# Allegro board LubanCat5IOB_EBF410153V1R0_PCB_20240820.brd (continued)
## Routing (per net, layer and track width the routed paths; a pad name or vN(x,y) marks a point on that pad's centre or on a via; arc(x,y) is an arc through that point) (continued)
I2C5_SCL_M3: length 267.7
  TOP w0.152: v1(47.28,32.16) 45.96,32.16 45.69,32.43 45.69,36.51 45.26,36.95 30.94,36.95 30.43,37.45 30.43,42.31 29.99,42.74 29.99,60.3 29.44,60.85 9.75,60.85 7.65,62.96 7.65,67.15 7.34,67.45 5.4,67.45 4.44,67.45 3.68,68.21 3.68,72.74 3.99,73.04 5.5,73.04 v1(5.97,72.57) ; R358.2 85.09,16.3 v2(85.64,16.85) 86.04,17.25 J2.92
  ART03 w0.152: v1(47.28,32.16) 47.79,31.64 57.61,31.64 60.07,29.17 63.65,29.17 64.14,29.66 76.1,29.66 76.89,30.44 v2(85.17,30.44)
  ART04 w0.152: v2(85.17,30.44) 85.17,17.33 v2(85.64,16.85)
  BOTTOM w0.152: v2(85.64,16.85) 86.48,16.02 93.88,16.02 95.28,14.62 123.52,14.62 127.88,18.98 140.6,18.98 141.42,19.8 141.42,29.22 141.72,29.52 157.19,29.52 157.56,29.89 157.56,30.94 157.99,31.38 169.53,31.38 170.55,32.4 170.55,54.32 169.91,54.96 J35.6 ; J15.9 v1(5.97,72.57)
I2C5_SDA_M3: length 267.1
  TOP w0.152: v1(48.28,32.16) 47.8,32.63 46.43,32.63 46.2,32.86 46.2,36.97 45.75,37.43 31.24,37.43 30.89,37.78 30.89,42.48 30.38,42.99 30.38,60.75 29.77,61.36 10.06,61.36 8.05,63.36 8.05,67.48 7.58,67.96 4.66,67.96 4.19,68.42 4.19,72.28 4.48,72.57 v1(4.97,72.57) ; J2.94 v2(86.44,17.69) 86.44,16.73 86.11,16.4 R359.2
  ART03 w0.152: v1(87.73,31.51) 77.06,31.51 75.67,30.11 64.01,30.11 63.83,30.29 59.84,30.29 57.98,32.16 v1(48.28,32.16)
  ART04 w0.152: v1(87.73,31.51) 87.73,31.51 86.44,30.22 v2(86.44,17.69)
  BOTTOM w0.152: J15.10 5.47,73.07 v1(4.97,72.57) ; v2(86.44,17.69) 86.44,16.83 86.87,16.4 95.28,16.4 95.69,15.99 111.56,15.99 112.39,15.15 122.45,15.15 126.73,19.43 140.41,19.43 140.97,19.99 140.97,29.67 141.27,29.97 156.74,29.97 157.05,30.28 157.05,31.52 157.4,31.88 169.42,31.88 170.05,32.51 170.05,54.11 169.71,54.46 J35.5
I2C7_SCL: length 36.5
  TOP w0.152: Q34.3 140.68,36.66 v1(140.72,36.7) ; J36.6 164.36,44.06 163.96,44.46 159.87,44.46 159.38,43.98 v1(159.38,37.46)
  BOTTOM w0.152: v1(159.38,37.46) 158.75,38.1 141.04,38.1 140.72,37.77 v1(140.72,36.7)
  BOTTOM w0.173: R331.2 v1(140.72,36.7)
I2C7_SCL_M0: length 195.8
  TOP w0.152: J2.77 83.24,23.39 83.39,23.54 83.39,31.18 v1(82.6,31.97) ; Q34.2 v1(142.71,36.66) ; U16.28 v1(19.1,78.37)
  ART03 w0.152: v1(82.6,31.97) 100.56,31.97 104.17,28.36 139.22,28.36 141.99,31.13 141.99,35.94 v1(142.71,36.66)
  ART04 w0.152: v1(82.6,31.97) 83.67,31.97 84.61,32.91 84.61,45.58 84.18,46.01 50.85,46.01 50.06,45.23 42.39,45.23 41.63,45.99 41.63,66.56 38.61,69.59 38.61,72.46 38.3,72.76 32.13,72.76 31.32,73.57 22.83,73.57 21.97,74.44 21.97,79.64 21.67,79.95 18.87,79.95 18.52,79.59 18.52,78.95 v1(19.1,78.37)
  BOTTOM w0.173: v1(142.71,36.66) 142.75,36.63 R332.2
I2C7_SDA: length 31.9
  TOP w0.152: Q33.3 v1(144.61,36.66) ; v1(158.39,37.46) 158.39,44.49 158.8,44.91 164.15,44.91 164.49,44.56 J36.5
  BOTTOM w0.152: v1(158.39,37.46) 145.41,37.46 v1(144.61,36.66)
  BOTTOM w0.173: v1(144.61,36.66) 144.78,36.5 R330.2
I2C7_SDA_M0: length 195.5
  TOP w0.152: v1(19.1,79.37) 19.55,78.92 U16.27 ; J2.75 82.84,28.66 82.5,29 82.5,31.28 82.14,31.64 v1(82.14,33.82) 82.14,41.95 v1(81.64,42.46) ; Q33.2 v1(146.65,36.66)
  ART03 w0.152: v1(82.14,33.82) 102.46,33.82 102.87,34.23 116.81,34.23 v1(117.59,33.44)
  ART04 w0.152: v1(81.64,42.46) 82.17,41.92 83.67,41.92 84.02,42.28 84.02,45.18 83.59,45.61 51.41,45.61 50.62,44.82 42.21,44.82 41.27,45.76 41.27,62.4 40.21,63.46 40.21,67.4 38.2,69.41 38.2,72.1 37.9,72.4 31.57,72.4 30.94,73.04 22.63,73.04 22,73.67 21.55,73.67 20.95,74.27 20.95,78.86 20.44,79.37 v1(19.1,79.37)
  BOTTOM w0.152: v1(117.59,33.44) 119.5,31.54 131.09,31.54 133.4,33.85 138.91,33.85 139.61,33.15 142.62,33.15 143.13,33.65 145.67,33.65 146.05,34.03 146.05,34.91 R329.2
  BOTTOM w0.173: R329.2 146.69,36.63 v1(146.65,36.66)
I2C8_SCL_M2: length 100.7
  TOP w0.152: J2.96 86.84,17.25 v2(87.24,16.85) 87.12,16.73 R356.2
  BOTTOM w0.152: J37.6 163.02,37.56 160.81,35.35 148.56,35.35 148.26,35.04 148.26,31.33 147.79,30.86 140.26,30.86 139.95,30.56 139.95,20.62 139.65,20.32 125.79,20.32 122.43,16.96 96.5,16.96 95.28,18.18 87.17,18.18 86.87,17.87 86.87,17.22 v2(87.24,16.85)
I2C8_SDA_M2: length 99.8
  TOP w0.152: R357.2 87.74,16.15 87.74,17.19 v2(87.24,17.69) J2.98
  BOTTOM w0.152: J37.5 163.13,37.06 160.99,34.91 148.97,34.91 148.67,34.61 148.67,30.93 148.1,30.36 140.8,30.36 140.45,30.01 140.45,20.12 140.15,19.82 126.15,19.82 122.05,15.71 112.62,15.71 111.91,16.42 96.03,16.42 95.13,17.32 87.61,17.32 v2(87.24,17.69)
I2S0_LRCK: length 119.5
  TOP w0.152: v1(82.64,43.46) 85.03,43.46 85.72,42.76 85.72,28.11 84.84,27.22 J2.85 ; v1(17.65,74.26) 17.75,74.36 U16.7
  ART04 w0.152: v1(17.65,74.26) 18.14,73.77 18.14,70.68 18.57,70.25 27.64,70.25 28.55,69.33 34.34,69.33 35.13,68.54 35.13,67.2 36.55,65.78 36.55,45.79 40.61,41.72 67.79,41.72 68.07,42 80.75,42 81.05,42.31 81.05,42.64 81.36,42.94 82.12,42.94 v1(82.64,43.46)
I2S0_MCLK: length 118.7
  TOP w0.152: J2.81 84.04,23.54 83.9,23.69 83.9,41.2 v1(82.64,42.46) ; U16.1 17.85,77.06 v1(17.65,77.26)
  ART04 w0.152: v1(17.65,77.26) 17.65,76.85 21.34,73.17 21.77,73.17 22.43,72.51 30.71,72.51 31.32,71.9 37.21,71.9 37.52,71.59 37.52,69.36 38.4,68.47 38.4,67.71 39.7,66.41 39.7,63.24 40.16,62.78 40.16,46.12 41.96,44.31 50.95,44.31 51.71,45.07 82.98,45.07 83.41,44.64 83.41,42.86 83.01,42.46 v1(82.64,42.46)
I2S0_SCLK: length 116.6
  TOP w0.152: J2.83 84.44,42.35 83.87,42.92 80.18,42.92 v1(79.64,43.46) ; U16.5 v1(17.65,75.26)
  ART04 w0.152: v1(17.65,75.26) 19.92,72.99 19.92,72.02 20.23,71.72 20.68,71.72 21.07,71.33 28.51,71.33 28.96,70.88 35.97,70.88 36.2,70.65 36.2,69.2 36.77,68.63 36.77,67.56 38.23,66.1 38.23,45.66 41.05,42.84 66.88,42.84 67.5,43.46 v1(79.64,43.46)
I2S0_SDI0: length 120.2
  TOP w0.152: v1(80.64,43.46) 81.67,44.49 85.78,44.49 86.69,43.58 86.69,27.68 85.64,26.63 J2.89 ; U16.8 19.1,73.41 18.94,73.26 v1(18.65,73.26)
  ART04 w0.152: v1(18.65,73.26) 19.05,72.86 19.05,70.93 19.23,70.75 27.86,70.75 28.75,69.86 31.55,69.86 32.03,70.35 34.92,70.35 35.23,70.04 35.23,69.38 35.73,68.89 35.73,67.46 37.49,65.7 37.49,61.71 37.26,61.48 37.26,45.84 40.82,42.28 67.21,42.28 67.79,42.86 80.05,42.86 v1(80.64,43.46)
I2S0_SDO0: length 124.9
  TOP w0.152: v1(81.64,43.46) 82.19,44.01 85.42,44.01 86.26,43.17 86.26,27.9 85.24,26.89 J2.87 ; v1(17.65,73.26) 17.14,73.76 17.14,74.56 17.39,74.81 U16.6
  ART04 w0.152: v1(81.64,43.46) 81.09,44.01 66.52,44.01 66.01,43.5 54.25,43.5 53.95,43.8 41.66,43.8 39.14,46.32 39.14,65.9 37.27,67.77 37.27,68.88 36.7,69.45 36.7,71.08 36.4,71.39 30.96,71.39 30.4,71.95 22.25,71.95 21.54,72.66 21.08,72.66 17.87,75.88 17.21,75.88 16.92,75.58 16.92,73.56 17.22,73.26 v1(17.65,73.26)
LCD0_BL_PWM: length 143.2
  TOP w0.152: J4.85 84.84,63.92 v2(84.44,63.52) ; J14.13 v1(8.13,77.07)
  ART04 w0.152: v1(29.09,78.45) 31.03,78.45 31.48,78.91 38.33,78.91 38.73,79.31 38.73,85.74 41.53,88.53 47.83,88.53 48.13,88.23 48.13,86.76 49.4,85.49 49.4,84.6 48.13,83.33 48.13,72.68 48.44,72.38 50.45,72.38 50.75,72.07 50.75,70.85 51.03,70.58 52.91,70.58 54.33,69.15 54.33,55.36 55.63,54.07 72.85,54.07 73.53,54.75 73.53,68.24 74.42,69.13 79.48,69.13 79.78,68.82 79.78,68.49 80.09,68.19 81.39,68.19 81.62,67.96 81.62,66.32 82.14,65.8 82.91,65.8 83.16,65.55 85.31,65.55 85.61,65.24 85.61,64.2 85.31,63.9 84.82,63.9 v2(84.44,63.52)
  BOTTOM w0.152: v1(8.13,77.07) 8.29,77.07 9.83,75.53 11.19,75.53 11.7,76.03 11.7,76.25 11.95,76.51 12.26,76.51 13.26,77.51 16.48,77.51 17.04,78.07 17.58,78.07 18.34,78.83 22.68,78.83 22.89,78.63 28.91,78.63 v1(29.09,78.45)
LCD0_PWR_EN: length 130.6
  TOP w0.152: v1(79.6,41.47) 79.64,41.43 79.64,29.48 79.17,29.01 79.17,27.85 79.4,27.62 79.4,23.31 79.64,23.07 J2.59
  ART03 w0.152: v1(34.21,43.04) 35.05,42.2 78.89,42.2 79.6,41.49 v1(79.6,41.47)
  BOTTOM w0.152: R306.1 12.95,81.47 13.26,81.17 22.94,81.17 23.62,81.85 34.85,81.85 35.26,81.45 35.26,64.28 34.82,63.85 33.48,63.85 33.12,63.49 33.12,57.39 33.58,56.94 33.58,43.68 v1(34.21,43.04)
LCD0_RST: length 166.6
  TOP w0.152: v1(125.78,44.33) 125.78,47.39 126.09,47.69 132.09,47.69 132.39,47.39 U44.18 ; J14.15 6.09,76.07 5.58,75.56 3.28,75.56 2.92,75.21 2.92,62.78 3.35,62.35 6.55,62.35 10.03,58.87 10.03,52.86 v1(9.58,52.4)
  ART03 w0.152: v1(125.78,44.33) 123.63,46.48 117.59,46.48 117.22,46.12 108.58,46.12 107.52,45.05 100.05,45.05 98.78,46.32 37.26,46.32 36.17,47.41 30.25,47.41 29.57,48.1 21.08,48.1 20.85,47.87 11.43,47.87 11.02,48.27 11.02,48.99 10.79,49.21 10.79,52.08 10.47,52.4 v1(9.58,52.4)
LCD1_BL_PWM: length 139.7
  TOP w0.152: J4.87 v2(85.24,64.36)
  ART04 w0.152: v1(29.09,77.45) 31.03,77.45 31.44,77.87 38.79,77.87 39.27,78.35 39.27,85.64 41.53,87.9 45.59,87.9 47.24,86.25 47.24,81.68 46.74,81.17 46.74,74.31 47.12,73.93 47.12,72.15 47.35,71.92 49.48,71.92 49.78,71.62 49.78,70.47 50.09,70.17 52.68,70.17 53.9,68.95 53.9,54.9 55.19,53.61 73.1,53.61 73.93,54.44 73.93,68.08 74.63,68.77 78.94,68.77 79.25,68.47 79.25,67.58 79.53,67.3 80.54,67.3 80.85,66.99 80.85,65.67 81.25,65.27 82.7,65.27 83.06,64.91 84.69,64.91 v2(85.24,64.36)
  BOTTOM w0.152: J15.13 7.95,74.57 8.18,74.79 8.18,75.55 8.46,75.83 8.91,75.83 9.57,75.17 11.84,75.17 13.23,76.57 16.23,76.57 17.35,77.69 18.19,77.69 18.52,77.36 19.68,77.36 20.27,77.94 22.76,77.94 23.09,77.61 28.93,77.61 v1(29.09,77.45)
LCD1_PWR_EN: length 93.6
  TOP w0.152: R305.1 28.19,64.03 28.38,63.84 29.62,63.84 30.26,63.2 33.49,63.2 v1(33.67,63.39) ; J2.61 80.04,23.3 79.76,23.59 79.76,27.6 80.04,27.88 80.04,42.06 v1(79.64,42.46)
  ART03 w0.152: v1(34.21,44.19) 35.64,42.76 79.34,42.76 v1(79.64,42.46)
  BOTTOM w0.152: v1(33.67,63.39) 33.53,63.24 33.53,58.05 34.16,57.42 34.16,44.24 v1(34.21,44.19)
LCD1_RST: length 172.1
  TOP w0.152: U44.20 133.69,48.39 133.38,48.71 124.09,48.71 123.78,48.4 v1(123.78,44.33)
  ART03 w0.152: v1(9.58,50.4) 9.58,47.06 10.03,46.6 25.22,46.6 25.55,46.27 35.23,46.27 35.97,45.53 97.43,45.53 100.28,42.69 103.3,42.69 103.86,43.25 108,43.25 109.33,44.58 123.54,44.58 v1(123.78,44.33)
  BOTTOM w0.152: v1(9.58,50.4) 9.07,50.91 9.07,56.79 8.71,57.15 7.52,57.15 6.5,58.16 5.03,58.16 4.72,58.47 4.72,59.66 4.37,60.02 2.69,60.02 2.29,60.43 2.29,75.18 2.67,75.56 7,75.56 J15.15
LOUT1: length 50.1
  TOP w0.203: U16.12 20.9,72.68 v1(21.32,72.26)
  ART03 w0.203: v1(36.59,90.45) 36.59,91.04 36.04,91.58 20.5,91.58 19.84,90.92 19.84,87.87 19.46,87.49 19.46,85.51 20.14,84.83 22.35,84.83 22.99,84.19 22.99,83.07 23.22,82.84 23.22,81.85 22.81,81.45 20.37,81.45 19.61,80.69 19.61,77.79 19.08,77.26 19.08,70.91 19.28,70.7 20.98,70.7 21.32,71.04 v1(21.32,72.26)
  BOTTOM w0.203: C122.1 36.79,90.65 v1(36.59,90.45)
LOUT2: length 10.4
  TOP w0.203: C279.1 26.42,68.34 23.88,68.34 23.62,68.59 23.62,73.55 22.81,74.36 U16.15
M2EKEY_3V3: length 18.8
  ART04 w0.254: 131.1,75.3 v1(131.1,74.54)
  BOTTOM w0.254: v1(131.1,74.54) 131.1,77.43 130.43,78.1 128.4,78.1 128.02,77.72 R147.1 ; 158.52,63.27 158,62.75 156.01,62.75 155.75,62.5 155.75,57.29 156.13,56.91 C128.2 R138.2
  vias: v1(123.7,62.39) v1(124.7,62.39) v1(141.4,66.38) v1(141.4,65.38) v1(159.57,64.46) v1(159.57,63.46) v1(160.57,64.46) v1(160.57,63.46)
M2EKEY_NWDISABLE: length 124.7
  TOP w0.152: v2(82.44,17.69) J2.74
  ART03 w0.152: v2(82.96,29.56) 87.96,29.56 89.28,30.88 100.14,30.88 103.57,27.45 140.51,27.45 143.63,30.57 143.63,37.21 145.4,38.97 145.4,56.68 145.09,56.99 135.41,56.99 135.1,57.29 135.1,59.41 134.8,59.71 128.7,59.71 v1(128.27,59.28)
  ART04 w0.152: v2(82.96,29.56) 82.96,18.21 v2(82.44,17.69)
  BOTTOM w0.152: R146.2 v1(128.27,59.28)
M2EKEY_PWR_EN: length 143.4
  TOP w0.152: v1(164.62,15.21) 164.62,31.13 164.31,31.43 156.54,31.43 156.24,31.74 156.24,45.23 155.93,45.53 154.91,45.53 154.64,45.81 154.64,48.89 154.97,49.22 155.3,49.22 155.57,49.5 155.57,51.89 155.23,52.23 155.23,53.42 v1(155.68,53.86) ; v2(80.84,17.69) J2.66
  BOTTOM w0.152: v2(80.84,17.69) 81.24,17.29 83.52,17.29 83.95,16.86 83.95,15.48 86.08,13.35 87.88,13.35 91.19,10.05 155.46,10.05 156.08,10.67 156.08,13.66 156.39,13.97 163.37,13.97 v1(164.62,15.21) ; R140.2 v1(155.68,53.86)
M2PCIE_3V3: length 24.8
  TOP w0.254: R237.2 v1(161.04,81.43) ; J19.2 152.03,86.45 C170.1 C171.1 ; C182.1 154.07,82.32 R236.2 ; J19.74 v1(170.04,85.3) ; C181.1 v1(157.11,81.42) ; J19.72 v1(169.54,87.62) ; J19.70 v1(169.04,85.3)
  ART03 w0.254: v1(158.11,81.42) 158.11,80.42 v1(158.11,80.42) v1(157.11,80.42) v1(157.11,81.42) ; v1(151.03,80.42) v1(151.03,81.42)
  ART04 w0.254: v1(151.32,72.36) 151.32,80.13 v1(151.03,80.42)
  BOTTOM w0.254: v1(151.32,72.36) 151.37,72.4 C157.2 R218.2
  vias: v1(151.03,83.42) v1(151.03,82.42)
M2PCIE_PWR_EN: length 146.1
  TOP w0.152: v1(150.32,69.36) 147.21,69.36 146.94,69.09 146.94,56.48 146.38,55.92 v1(144.45,55.92) ; v1(67.64,48.22) 65.96,48.22 65.53,47.79 65.53,38.04 65.23,37.73 53.58,37.73 53.27,37.43 J1.55
  ART03 w0.152: v1(67.64,48.22) 67.72,48.15 76.1,48.15 76.28,48.33 76.28,49.11 76.58,49.42 80.72,49.42 81.1,49.04 84.02,49.04 84.93,49.94 116.14,49.94 116.92,49.16 123.14,49.16 123.47,49.49 144.15,49.49 144.45,49.8 v1(144.45,55.92)
  BOTTOM w0.152: R221.2 v1(150.32,69.36)
M2PCIE_REF_CLKN: length 108.9
  TOP w0.114: J19.53 164.79,92.98 164.92,92.85 164.92,89.05 v1(164.63,88.76)
  BOTTOM w0.114: v1(164.63,88.76) 164.85,88.98 arc(164.9,89.06) 164.92,89.15 164.92,89.85 arc(165.06,90.19) 165.39,90.32 165.74,90.32 arc(166.07,90.19) 166.2,89.85 166.2,88.46 arc(166.09,87.86) 165.75,87.35 163.58,85.18 163.33,84.94 arc(163.08,84.56) 162.99,84.11 162.99,80.71 arc(162.86,80.04) 162.48,79.48 161.96,78.95 arc(161.53,78.67) 161.02,78.56 158.95,78.56 arc(158.23,78.42) 157.61,78.01 157.53,77.92 156.65,77.04 arc(155.91,76.55) 155.04,76.38 154.46,76.38 arc(153.64,76.22) 152.96,75.75 150.29,73.09 arc(149.48,71.88) 149.2,70.45 149.2,66.63 149.17,66.27 148.65,63.28 149.17,60.29 149.2,59.93 149.2,55.1 arc(149.09,54.53) 148.76,54.05 147.49,52.78 147.48,52.76 arc(147.07,52.49) 146.58,52.39 139.08,52.39 arc(139.07,52.39) 139.05,52.39 135.6,51.79 arc(135.52,51.78) 135.44,51.79 132,52.39 arc(131.98,52.39) 131.96,52.39 129.52,52.39 arc(128.68,52.22) 127.97,51.75 126.98,50.76 arc(126.38,50.36) 125.68,50.22 118.03,50.22 arc(118.01,50.22) 117.99,50.21 114.59,49.62 arc(114.51,49.62) 114.43,49.62 111.03,50.21 arc(111.01,50.22) 110.99,50.22 110.59,50.22 arc(110.57,50.22) 110.55,50.21 106.01,49.43 arc(105.93,49.42) 105.85,49.43 arc(105.84,49.43) 105.83,49.43 arc(105.82,49.43) 105.81,49.43 100.79,49.43 100.33,48.98 100.33,46.45 100.56,46.22 101.73,46.22 v1(102.12,46.61)
M2PCIE_REF_CLKP: length 108.9
  TOP w0.114: J19.55 165.29,92.98 165.16,92.85 165.16,89.99 arc(165.2,89.91) 165.28,89.87 arc(165.37,89.83) 165.4,89.75 165.4,89.53 arc(165.37,89.45) 165.28,89.41 arc(165.2,89.38) 165.16,89.29 165.16,89.05 v1(165.45,88.76)
  BOTTOM w0.114: v1(102.12,45.59) 101.73,45.98 100.46,45.98 100.09,46.35 100.09,49.08 100.69,49.67 105.81,49.67 arc(105.85,49.67) 105.89,49.67 arc(105.93,49.66) 105.97,49.66 110.51,50.45 arc(110.55,50.46) 110.59,50.46 110.99,50.46 arc(111.03,50.46) 111.07,50.45 114.47,49.86 arc(114.51,49.86) 114.55,49.86 117.95,50.45 arc(117.99,50.46) 118.03,50.46 125.68,50.46 arc(126.29,50.58) 126.81,50.93 127.8,51.92 arc(128.59,52.45) 129.52,52.63 131.96,52.63 arc(132,52.63) 132.04,52.62 135.48,52.03 arc(135.52,52.02) 135.56,52.03 139,52.62 arc(139.04,52.63) 139.08,52.63 146.58,52.63 arc(146.98,52.71) 147.31,52.93 147.32,52.95 148.59,54.22 arc(148.86,54.62) 148.96,55.1 148.96,59.92 148.93,60.26 148.4,63.28 148.93,66.3 148.96,66.64 148.96,70.45 arc(149.26,71.97) 150.12,73.26 152.79,75.93 arc(153.55,76.44) 154.46,76.62 155.04,76.62 arc(155.82,76.77) 156.48,77.21 157.36,78.09 157.44,78.18 arc(158.14,78.64) 158.95,78.81 161.02,78.81 arc(161.43,78.89) 161.79,79.12 162.31,79.65 arc(162.64,80.14) 162.75,80.71 162.75,84.11 arc(162.86,84.65) 163.16,85.11 163.41,85.35 165.58,87.52 arc(165.86,87.95) 165.96,88.46 165.96,89.85 arc(165.9,90.02) 165.74,90.08 165.39,90.08 arc(165.23,90.02) 165.16,89.85 165.16,89.15 arc(165.18,89.06) 165.23,88.98 v1(165.45,88.76)
MASKROM: length 6.8
  TOP w0.152: R1.1 25.92,14.87 D2.2 ; SW1.2 27.34,11.54 26.93,11.94 D2.2 ; D2.2 C4.1
MDIN0_PHY0: length 1.8
  TOP w0.114: U4.2 71.86,80.75 71.94,80.84 71.94,81.15 72.31,81.52 72.32,81.52 72.32,81.71 R366.1
MDIN0_PHY0_RJ45: length 7.8
  TOP w0.114: R366.2 72.32,82.66 72.32,83.08 73.2,83.96 75.14,83.96 75.37,84.19 75.37,85.84 75.14,86.07 74.53,86.07 74.3,85.84 J6.3
MDIN0_PHY1: length 1.8
  TOP w0.114: R374.1 53.92,81.71 53.92,81.52 53.91,81.52 53.54,81.15 53.54,80.84 53.46,80.75 U3.2
MDIN0_PHY1_RJ45: length 8.1
  TOP w0.114: R374.2 53.92,82.66 53.92,83.08 54.29,83.45 56.74,83.45 56.97,83.68 56.97,85.84 56.74,86.07 56.13,86.07 55.9,85.84 J7.3
MDIN1_PHY0: length 1.8
  TOP w0.114: R368.1 71.03,81.73 71.03,81.56 70.74,81.27 70.74,80.85 70.66,80.77 U4.5
MDIN1_PHY0_RJ45: length 13.9
  TOP w0.114: R368.2 70.85,82.78 71.05,82.98 71.05,83.55 71.56,84.06 72.24,84.06 72.93,84.76 72.93,85.66 71.68,86.92 71.68,88.55 71.44,88.79 69.4,88.79 69.22,88.61 J6.7
MDIN1_PHY1: length 1.8
  TOP w0.114: U3.5 52.26,80.77 52.34,80.85 52.34,81.27 52.63,81.56 52.63,81.73 R376.1
MDIN1_PHY1_RJ45: length 14
  TOP w0.114: R376.2 52.45,82.78 52.65,82.98 52.65,83.55 53.16,84.06 53.84,84.06 54.53,84.76 54.53,85.66 53.28,86.92 53.28,88.69 53.14,88.83 51.11,88.83 50.82,88.53 J7.7
MDIN2_PHY0: length 1.7
  TOP w0.114: U4.7 69.86,80.76 69.94,80.84 69.94,81.24 69.78,81.4 69.78,81.71 R370.1
MDIN2_PHY0_RJ45: length 5.7
  TOP w0.114: R370.2 69.58,82.78 69.78,82.98 69.78,83.4 70.32,83.94 70.32,87.58 J6.6
MDIN2_PHY1: length 1.7
  TOP w0.114: R378.1 51.38,81.71 51.38,81.4 51.54,81.24 51.54,80.84 51.46,80.76 U3.7
MDIN2_PHY1_RJ45: length 5.7
  TOP w0.114: J7.6 51.92,87.58 51.92,83.94 51.38,83.4 51.38,82.98 51.18,82.78 R378.2
MDIN3_PHY0: length 1.7
  TOP w0.114: R372.1 68.49,81.73 68.49,81.4 68.72,81.16 68.72,80.84 68.66,80.78 U4.10
MDIN3_PHY0_RJ45: length 5.7
  TOP w0.114: J6.9 66.68,85.83 66.87,86.02 67.71,86.02 67.9,85.83 67.9,84.06 68.51,83.46 68.51,82.98 68.31,82.78 R372.2
MDIN3_PHY1: length 1.7
  TOP w0.114: R380.1 50.09,81.73 50.09,81.4 50.32,81.16 50.32,80.84 50.26,80.78 U3.10
MDIN3_PHY1_RJ45: length 5.7
  TOP w0.114: R380.2 49.91,82.78 50.11,82.98 50.11,83.46 49.5,84.06 49.5,85.79 49.28,86.02 48.51,86.02 48.28,85.79 J7.9
MDIP0_PHY0: length 1.8
  TOP w0.114: U4.1 72.26,80.78 72.18,80.85 72.18,81.05 72.41,81.28 72.42,81.28 72.56,81.42 72.56,81.71 R365.1
MDIP0_PHY0_RJ45: length 7.8
  TOP w0.114: R365.2 72.56,82.66 72.56,82.98 73.3,83.72 75.24,83.72 75.61,84.09 75.61,87.71 J6.2
MDIP0_PHY1: length 1.8
  TOP w0.114: U3.1 53.86,80.78 53.78,80.85 53.78,81.05 54.01,81.28 54.02,81.28 54.16,81.42 54.16,81.71 R373.1
MDIP0_PHY1_RJ45: length 8.1
  TOP w0.114: R373.2 54.16,82.66 54.16,82.98 54.39,83.21 56.84,83.21 57.21,83.58 57.21,87.71 J7.2
MDIP1_PHY0: length 1.8
  TOP w0.114: U4.4 71.06,80.76 70.98,80.84 70.98,81.17 71.27,81.46 71.27,81.69 R367.1
MDIP1_PHY0_RJ45: length 13.9
  TOP w0.114: R367.2 71.49,82.78 71.29,82.98 71.29,83.45 71.66,83.82 72.34,83.82 73.18,84.66 73.18,85.76 71.92,87.02 71.92,88.65 71.54,89.03 71.01,89.03 70.82,89.22 70.82,89.68 70.94,89.8 72.72,89.8 73.03,89.49 J6.4
MDIP1_PHY1: length 1.8
  TOP w0.114: R375.1 52.87,81.69 52.87,81.46 52.58,81.17 52.58,80.84 52.66,80.76 U3.4
MDIP1_PHY1_RJ45: length 14
  TOP w0.114: J7.4 54.63,89.45 54.3,89.78 52.57,89.78 52.35,89.56 52.35,89.28 52.57,89.07 53.24,89.07 53.52,88.79 53.52,87.02 54.78,85.76 54.78,84.66 53.94,83.82 53.26,83.82 52.89,83.45 52.89,82.98 53.09,82.78 R375.2
MDIP2_PHY0: length 1.7
  TOP w0.114: R369.1 70.03,81.72 70.03,81.5 70.18,81.34 70.18,80.85 70.26,80.77 U4.6
MDIP2_PHY0_RJ45: length 5.7
  TOP w0.114: J6.5 71.76,85.88 71.6,86.04 70.72,86.04 70.56,85.88 70.56,83.84 70.02,83.3 70.02,82.98 70.22,82.78 R369.2
MDIP2_PHY1: length 1.7
  TOP w0.114: U3.6 51.86,80.77 51.78,80.85 51.78,81.34 51.63,81.5 51.63,81.72 R377.1
MDIP2_PHY1_RJ45: length 5.7
  TOP w0.114: J7.5 53.36,85.85 53.17,86.04 52.35,86.04 52.16,85.85 52.16,83.84 51.62,83.3 51.62,82.98 51.82,82.78 R377.2
MDIP3_PHY0: length 1.8
  TOP w0.114: U4.9 69.06,80.72 68.96,80.82 68.96,81.26 68.74,81.48 68.74,81.71 R371.1
MDIP3_PHY0_RJ45: length 5.7
  TOP w0.114: J6.8 68.15,87.55 68.15,84.16 68.75,83.56 68.75,82.98 68.95,82.78 R371.2
MDIP3_PHY1: length 1.8
  TOP w0.114: R379.1 50.34,81.71 50.34,81.48 50.56,81.26 50.56,80.82 50.66,80.72 U3.9
MDIP3_PHY1_RJ45: length 5.7
  TOP w0.114: J7.8 49.75,87.55 49.75,84.16 50.35,83.56 50.35,82.98 50.55,82.78 R379.2
MIC1N: length 41.8
  TOP w0.152: C113.2 v1(20.45,82.31)
  BOTTOM w0.152: v1(20.45,82.31) 20.14,82.62 20.14,83.05 20.45,83.35 22.17,83.35 23.06,84.24 39.75,84.24 43.03,87.52 43.03,92.83 43.71,93.52 43.71,96.91 43.15,97.47 38.8,97.47 R117.2
MIC1P: length 42.4
  TOP w0.152: C112.2 v1(19.43,82.31)
  BOTTOM w0.152: v1(19.43,82.31) 19.79,82.67 19.79,83.19 20.3,83.71 22.02,83.71 22.91,84.6 39.6,84.6 42.67,87.67 42.67,92.98 43.36,93.66 43.36,96.76 43,97.12 38.14,97.12 R114.2
MIC2N: length 23.2
  TOP w0.152: C117.2 v1(22.48,82.31) ; R134.2 v1(3.94,86.88)
  ART03 w0.152: v1(3.94,86.88) 3.63,86.58 3.63,85.81 4.01,85.44 8.43,85.44 10.41,83.45 21.9,83.45 22.2,83.15 22.2,82.59 v1(22.48,82.31)
MIC2P: length 23.3
  TOP w0.152: C115.2 v1(21.46,82.31) ; R130.2 v1(2.92,86.88)
  ART03 w0.152: v1(2.92,86.88) 3.28,86.53 3.28,85.66 3.86,85.08 8.28,85.08 10.26,83.1 21.69,83.1 21.84,82.95 21.84,82.69 v1(21.46,82.31)
MINIPCIE_3V3: length 45.9
  TOP w0.254: J23.39 126.1,73.21 125.77,73.54 v1(125.76,73.54) 125.74,73.54 125.3,73.1 J23.41
  TOP w0.381: v1(144.91,60.32) C223.1 J23.2 ; J23.24 132.1,60.34 C221.1 131.49,60.32 v1(131.32,60.49) v1(130.52,60.49) ; C220.1 120.9,63.88 J23.52
  ART04 w0.254: v1(144.53,77.98) 144.53,76.25 144.93,75.84 148.18,75.84 148.69,75.34 148.69,66.22 149.2,65.72 v1(150.08,65.72)
  ART04 w0.508: v1(125.76,74.56) v1(125.76,73.54)
  BOTTOM w0.254: R254.1 C200.1 151.85,57.22 150.34,57.22 150.09,57.47 150.09,62.68 150.34,62.93 151.7,62.93 C203.1 ; R264.1 v1(144.53,77.98)
  vias: v1(122.78,60.32) v1(123.78,60.32) v1(144.91,61.32) v1(150.08,64.72) v1(150.08,63.72) v1(150.83,65.72) v1(150.83,64.72) v1(150.83,63.72)
MINIPCIE_NWDISABLE: length 88.9
  TOP w0.152: v2(76.45,66.18) 76.04,66.6 J4.42 ; R267.2 v1(134.11,58.55)
  ART03 w0.152: v1(75.78,48.63) 75.78,49.42 76.17,49.8 79.12,49.8 79.54,50.21 80.04,50.21 80.35,49.9 80.93,49.9 81.34,49.49 83.67,49.49 84.66,50.48 128.7,50.48 129.72,51.5 133.43,51.5 134.11,52.19 v1(134.11,58.55)
  ART04 w0.152: v1(75.78,48.63) 77.24,50.09 77.24,65.39 v2(76.45,66.18)
MINIPCIE_PWR_EN: length 110.9
  TOP w0.152: v1(150.13,53.7) 149.56,53.7 149.17,53.31 149.17,43.25 149.52,42.9 151.21,42.9 151.59,42.52 v1(151.59,40.89) ; J2.71 82.04,22.74 82.42,23.12 82.42,28.46 82.02,28.87 82.02,31.03 81.64,31.41 81.64,41.45 v1(81.64,41.46)
  ART03 w0.152: v1(113.84,43.18) 113.22,42.56 110.36,42.56 107.82,40.02 83.08,40.02 v1(81.64,41.46)
  BOTTOM w0.152: v1(150.13,53.7) 150.29,53.86 R262.1 ; v1(113.84,43.18) 114.81,42.2 130.05,42.2 130.75,41.5 150.98,41.5 v1(151.59,40.89)
MIPI_CSI0_CLK0N: length 167.5
  TOP w0.114: v2(66.29,22.39) 66.51,22.17 66.51,19.15 65.28,17.92 65.28,16.02 63.14,13.88 52.86,13.88 52.39,14.34 52.39,17.96 52.47,18.04 J1.52 ; v1(164.39,59.3) 164.68,59.59 165.01,59.59 165.14,59.46 J34.10
  ART03 w0.102: v2(66.29,22.39) 66.59,22.69 66.59,23.04 66.96,23.41 67.24,23.41 arc(67.32,23.44) 67.35,23.52 arc(67.39,23.6) 67.47,23.64 67.65,23.64 arc(67.73,23.6) 67.76,23.52 arc(67.79,23.44) 67.87,23.41 68.05,23.41 arc(68.13,23.44) 68.17,23.52 arc(68.2,23.6) 68.28,23.64 68.46,23.64 arc(68.54,23.6) 68.57,23.52 arc(68.61,23.44) 68.69,23.41 68.87,23.41 arc(68.95,23.44) 68.98,23.52 arc(69.01,23.6) 69.09,23.64 69.27,23.64 arc(69.35,23.6) 69.39,23.52 arc(69.42,23.44) 69.5,23.41 69.68,23.41 arc(69.76,23.44) 69.79,23.52 arc(69.83,23.6) 69.91,23.64 70.08,23.64 arc(70.17,23.6) 70.2,23.52 arc(70.23,23.44) 70.31,23.41 70.49,23.41 arc(70.57,23.44) 70.6,23.52 arc(70.64,23.6) 70.72,23.64 70.9,23.64 arc(70.98,23.6) 71.01,23.52 arc(71.04,23.44) 71.13,23.41 100.01,23.41 102.71,20.72 114.92,20.72 116.85,22.65 148.39,22.65 149.1,23.36 149.1,28.32 149.76,28.99 149.76,34.9 149.45,35.21 149.45,52.97 149.82,53.34 152.7,53.34 153.87,54.51 157.05,54.51 157.25,54.71 157.25,58.45 157.65,58.85 161.89,58.85 162.33,58.41 162.33,57.9 162.53,57.7 163.47,57.7 163.97,58.19 164.97,58.19 165.19,58.41 165.19,59.36 164.98,59.57 164.66,59.57 v1(164.39,59.3)
MIPI_CSI0_CLK0P: length 167.5
  TOP w0.114: v1(164.39,60.11) 164.68,59.83 165.01,59.83 165.14,59.96 J34.9 ; J1.50 52.07,18.04 52.15,17.96 52.15,14.24 52.76,13.64 63.24,13.64 65.52,15.92 65.52,17.82 66.75,19.05 66.75,22.07 v2(67.07,22.39)
  ART03 w0.102: v1(164.39,60.11) 164.66,59.85 165.1,59.85 165.47,59.48 165.47,58.29 165.09,57.91 164.08,57.91 163.59,57.42 162.42,57.42 162.05,57.78 162.05,58.29 161.78,58.57 157.76,58.57 157.53,58.33 157.53,54.59 157.16,54.23 153.99,54.23 152.82,53.06 149.94,53.06 149.73,52.86 149.73,35.32 150.04,35.02 150.04,28.87 149.38,28.21 149.38,23.24 148.5,22.37 116.97,22.37 115.04,20.44 102.59,20.44 99.9,23.13 67.07,23.13 66.87,22.93 66.87,22.59 v2(67.07,22.39)
MIPI_CSI0_CLK1N: length 168.9
  TOP w0.114: v2(49.44,20.29) 49.18,20.03 49.18,19.71 49.27,19.61 J1.36
  ART03 w0.102: v1(164.34,57.11) 164.07,56.85 163.33,56.85 162.89,56.4 162.89,56.11 162.76,55.99 162.76,55.71 162.89,55.58 162.89,55.3 162.76,55.17 162.76,54.89 162.89,54.77 162.89,54.49 162.76,54.36 162.76,54.08 162.89,53.95 162.89,53.68 162.76,53.55 162.76,53.27 162.89,53.14 162.89,50.71 162.52,50.34 153.83,50.34 153.03,49.55 153.03,16.4 152.16,15.52 140.61,15.52 139.22,16.91 126.19,16.91 125.07,15.79 93.24,15.79 93.04,15.99 93.04,18.07 92.66,18.46 55.13,18.46 54.76,18.09 54.76,16.07 54.56,15.86 49.5,15.86 49.19,16.18 49.19,20.04 v2(49.44,20.29)
  BOTTOM w0.114: v1(164.34,57.11) 164.63,56.83 165.01,56.83 165.14,56.96 J35.10
MIPI_CSI0_CLK1P: length 168.9
  TOP w0.114: v2(48.66,20.29) 48.94,20.01 48.94,19.68 48.87,19.61 J1.34
  ART03 w0.102: v1(164.34,56.3) 164.07,56.57 163.45,56.57 163.17,56.29 163.17,50.6 162.63,50.06 153.94,50.06 153.31,49.43 153.31,16.28 152.27,15.24 140.49,15.24 139.1,16.63 126.3,16.63 125.19,15.51 93.13,15.51 92.76,15.88 92.76,17.96 92.54,18.18 55.24,18.18 55.04,17.97 55.04,15.95 54.67,15.59 49.39,15.59 48.91,16.07 48.91,20.04 v2(48.66,20.29)
  BOTTOM w0.114: v1(164.34,56.3) 164.63,56.59 165.01,56.59 165.14,56.46 J35.9
MIPI_CSI0_D0N: length 167.6
  TOP w0.114: J34.12 165.14,58.46 165.01,58.59 163.1,58.59 v1(162.81,58.3) ; v2(63.92,24.55) 64.19,24.28 64.19,19.5 63.25,18.56 63.25,16.65 62.18,15.59 55.08,15.59 54.39,16.27 54.39,17.96 54.47,18.04 J1.62
  ART03 w0.102: v2(63.92,24.55) 64.18,24.82 64.18,25.83 64.63,26.28 73.89,26.28 74.4,25.77 101.13,25.77 102.2,24.7 107.05,24.7 107.33,24.42 107.33,23.88 107.45,23.76 107.62,23.76 107.74,23.88 107.74,24.52 108.02,24.81 108.42,24.81 108.71,24.52 108.71,23.88 108.83,23.76 108.99,23.76 109.11,23.88 109.11,24.42 109.4,24.7 146.34,24.7 146.74,25.1 146.74,28.58 147.62,29.47 147.62,54.74 148.23,55.35 151.99,55.35 153.15,56.5 155.22,56.5 155.42,56.71 155.42,61.45 155.79,61.81 163.2,61.81 163.85,61.16 163.85,58.93 163.49,58.57 163.08,58.57 v1(162.81,58.3)
MIPI_CSI0_D0P: length 167.6
  TOP w0.114: v2(64.7,24.55) 64.43,24.28 64.43,19.4 63.49,18.46 63.49,16.55 62.28,15.34 54.98,15.34 54.15,16.17 54.15,17.96 54.07,18.04 J1.60 ; v1(162.81,59.11) 163.1,58.83 165.01,58.83 165.14,58.96 J34.11
  ART03 w0.102: v1(162.81,59.11) 163.08,58.85 163.37,58.85 163.57,59.05 163.57,61.05 163.09,61.53 155.91,61.53 155.7,61.33 155.7,56.59 155.34,56.23 153.27,56.23 152.11,55.07 148.35,55.07 147.9,54.63 147.9,29.35 147.02,28.46 147.02,24.98 146.46,24.42 109.51,24.42 109.39,24.31 109.39,23.77 109.11,23.48 108.71,23.48 108.43,23.77 108.43,24.41 108.31,24.53 108.14,24.53 108.02,24.41 108.02,23.77 107.74,23.48 107.34,23.48 107.06,23.77 107.06,24.31 106.94,24.42 102.08,24.42 101.02,25.49 74.28,25.49 73.77,26 67.19,26 arc(67.13,25.97) 67.1,25.91 arc(67.07,25.85) 67.01,25.82 66.78,25.82 arc(66.72,25.85) 66.69,25.91 arc(66.67,25.97) 66.6,26 66.38,26 arc(66.31,25.97) 66.29,25.91 arc(66.26,25.85) 66.2,25.82 65.97,25.82 arc(65.91,25.85) 65.88,25.91 arc(65.85,25.97) 65.79,26 65.56,26 arc(65.5,25.97) 65.47,25.91 arc(65.45,25.85) 65.38,25.82 65.16,25.82 arc(65.09,25.85) 65.07,25.91 arc(65.04,25.97) 64.98,26 64.74,26 64.46,25.72 64.46,24.79 v2(64.7,24.55)
MIPI_CSI0_D1N: length 167.5
  TOP w0.114: J34.8 165.14,60.46 165.01,60.59 162.34,60.59 v1(162.05,60.3) ; v2(65.1,23.33) 65.37,23.06 65.37,19.41 64.26,18.3 64.26,16.27 62.71,14.72 54.13,14.72 53.59,15.26 53.59,17.96 53.67,18.04 J1.58
  ART03 w0.102: v2(65.1,23.33) 65.33,23.56 65.33,24.18 65.7,24.55 66.03,24.55 arc(66.11,24.58) 66.14,24.67 arc(66.17,24.75) 66.25,24.78 66.43,24.78 arc(66.51,24.75) 66.55,24.67 arc(66.58,24.58) 66.66,24.55 66.84,24.55 arc(66.92,24.58) 66.95,24.67 arc(66.99,24.75) 67.07,24.78 67.24,24.78 arc(67.33,24.75) 67.36,24.67 arc(67.39,24.58) 67.47,24.55 67.65,24.55 arc(67.73,24.58) 67.77,24.67 arc(67.8,24.75) 67.88,24.78 68.06,24.78 arc(68.14,24.75) 68.17,24.67 arc(68.2,24.58) 68.29,24.55 68.46,24.55 arc(68.54,24.58) 68.58,24.67 arc(68.61,24.75) 68.69,24.78 68.87,24.78 arc(68.95,24.75) 68.98,24.67 arc(69.02,24.58) 69.1,24.55 69.28,24.55 arc(69.36,24.58) 69.39,24.67 arc(69.42,24.75) 69.5,24.78 69.68,24.78 arc(69.76,24.75) 69.8,24.67 arc(69.83,24.58) 69.91,24.55 100.58,24.55 102.46,22.67 109.85,22.67 109.97,22.79 109.97,23.63 110.25,23.92 110.65,23.92 110.94,23.63 110.94,22.79 111.06,22.67 111.22,22.67 111.34,22.79 111.34,23.63 111.63,23.92 112.03,23.92 112.31,23.63 112.31,22.79 112.43,22.67 114.48,22.67 115.29,23.48 147.66,23.48 148.16,23.98 148.16,28.55 148.51,28.91 148.51,53.49 149.36,54.34 152.32,54.34 153.48,55.5 156.16,55.5 156.36,55.7 156.36,59.45 156.73,59.82 162.55,59.82 162.81,60.08 162.81,60.36 162.61,60.57 162.32,60.57 v1(162.05,60.3)
MIPI_CSI0_D1P: length 167.5
  TOP w0.114: J1.56 53.27,18.04 53.35,17.96 53.35,15.16 54.03,14.48 62.81,14.48 64.5,16.17 64.5,18.2 65.61,19.31 65.61,23.06 v2(65.88,23.33) ; J34.7 165.14,60.96 165.01,60.83 162.34,60.83 v1(162.05,61.11)
  ART03 w0.102: v1(162.05,61.11) 162.32,60.85 162.72,60.85 163.09,60.48 163.09,59.96 162.67,59.54 156.84,59.54 156.64,59.33 156.64,55.59 156.27,55.22 153.59,55.22 152.43,54.06 149.48,54.06 148.79,53.38 148.79,28.79 148.44,28.44 148.44,23.87 147.78,23.21 115.41,23.21 114.59,22.39 112.31,22.39 112.03,22.68 112.03,23.52 111.91,23.64 111.74,23.64 111.62,23.52 111.62,22.68 111.34,22.39 110.94,22.39 110.66,22.68 110.66,23.52 110.54,23.64 110.37,23.64 110.25,23.52 110.25,22.68 109.97,22.39 102.35,22.39 100.47,24.27 65.81,24.27 65.61,24.07 65.61,23.6 v2(65.88,23.33)
MIPI_CSI0_D2N: length 168.9
  TOP w0.114: v2(51.44,20.29) 51.18,20.03 51.18,19.71 51.27,19.61 J1.46
  ART03 w0.102: v1(161.54,58.11) 161.28,57.85 161.05,57.85 arc(160.98,57.88) 160.95,57.95 arc(160.92,58.02) 160.85,58.05 160.65,58.05 arc(160.57,58.02) 160.54,57.95 arc(160.51,57.88) 160.44,57.85 160.24,57.85 arc(160.17,57.88) 160.14,57.95 arc(160.11,58.02) 160.04,58.05 159.83,58.05 arc(159.76,58.02) 159.73,57.95 arc(159.7,57.88) 159.63,57.85 158.56,57.85 158.19,57.48 158.19,52.54 157.99,52.34 150.87,52.34 150.49,51.96 150.49,48.09 150.88,47.7 150.88,18.44 150.25,17.82 141.77,17.82 140.32,19.27 123.99,19.27 122.59,17.87 116.39,17.87 116.27,17.99 116.27,18.35 115.99,18.63 115.59,18.63 115.31,18.35 115.31,17.99 115.19,17.87 115.02,17.87 114.9,17.99 114.9,18.35 114.62,18.63 114.22,18.63 113.94,18.35 113.94,17.99 113.82,17.87 113.65,17.87 113.53,17.99 113.53,18.35 113.25,18.63 112.85,18.63 112.56,18.35 112.56,17.99 112.45,17.87 112.22,17.87 112.01,18.07 112.01,19.03 111.65,19.4 106.95,19.4 106.58,19.03 106.58,18.07 106.38,17.87 95.12,17.87 95.02,17.97 95.02,20.77 94.59,21.2 52.89,21.2 52.53,20.83 52.53,19.57 52.32,19.37 51.39,19.37 51.19,19.57 51.19,20.04 v2(51.44,20.29)
  BOTTOM w0.114: v1(161.54,58.11) 161.83,57.83 165.01,57.83 165.14,57.96 J35.12
MIPI_CSI0_D2P: length 168.9
  TOP w0.114: J1.44 50.87,19.61 50.94,19.68 50.94,20.01 v2(50.66,20.29)
  ART03 w0.102: v2(50.66,20.29) 50.91,20.04 50.91,19.46 51.27,19.09 52.44,19.09 52.81,19.46 52.81,20.72 53.01,20.92 94.47,20.92 94.74,20.65 94.74,17.86 95.01,17.59 106.49,17.59 106.86,17.96 106.86,18.91 107.06,19.12 111.53,19.12 111.73,18.91 111.73,17.96 112.1,17.59 112.56,17.59 112.84,17.87 112.84,18.23 112.96,18.35 113.13,18.35 113.25,18.23 113.25,17.87 113.53,17.59 113.93,17.59 114.22,17.87 114.22,18.23 114.33,18.35 114.5,18.35 114.62,18.23 114.62,17.87 114.9,17.59 115.3,17.59 115.59,17.87 115.59,18.23 115.71,18.35 115.87,18.35 115.99,18.23 115.99,17.87 116.28,17.59 122.71,17.59 124.1,18.99 140.21,18.99 141.66,17.54 150.37,17.54 151.16,18.33 151.16,47.82 150.77,48.21 150.77,51.84 150.98,52.06 158.1,52.06 158.47,52.43 158.47,57.37 158.67,57.57 161.27,57.57 v1(161.54,57.3)
  BOTTOM w0.114: J35.11 165.14,57.46 165.01,57.59 161.83,57.59 v1(161.54,57.3)
MIPI_CSI0_D3N: length 168.8
  TOP w0.114: v2(50.69,17.37) 50.41,17.65 50.41,17.98 50.47,18.04 J1.42
  ART03 w0.102: v2(50.69,17.37) 50.44,17.12 50.44,16.83 50.64,16.63 50.87,16.63 arc(51,16.68) 51.05,16.8 arc(51.1,16.93) 51.22,16.98 51.28,16.98 arc(51.4,16.93) 51.45,16.8 arc(51.51,16.68) 51.63,16.63 53.19,16.63 53.39,16.83 53.39,18.93 53.83,19.37 93.57,19.37 94.06,18.89 94.06,17.26 94.26,17.06 107.25,17.06 107.37,17.18 107.37,18.43 107.66,18.71 108.06,18.71 108.34,18.43 108.34,17.18 108.46,17.06 108.63,17.06 108.75,17.18 108.75,18.43 109.03,18.71 109.43,18.71 109.71,18.43 109.71,17.18 109.83,17.06 110.06,17.06 110.18,17.18 110.18,18.22 110.46,18.51 110.86,18.51 111.14,18.22 111.14,17.18 111.26,17.06 123.68,17.06 124.52,17.9 140,17.9 140.97,16.93 151.79,16.93 152.04,17.19 152.04,49.79 153.6,51.34 158.82,51.34 159.28,51.81 159.28,55.17 159.9,55.79 161.22,55.79 v1(161.54,56.11)
  BOTTOM w0.114: v1(161.54,56.11) 161.83,55.83 165.01,55.83 165.14,55.96 J35.8
MIPI_CSI0_D3P: length 168.8
  TOP w0.114: J1.40 50.07,18.04 50.17,17.95 50.17,17.62 v2(49.91,17.37)
  ART03 w0.102: v1(161.54,55.3) 161.33,55.51 160.02,55.51 159.56,55.06 159.56,51.69 158.93,51.06 153.71,51.06 152.32,49.67 152.32,17.07 151.91,16.65 140.85,16.65 139.89,17.62 124.64,17.62 123.8,16.78 111.15,16.78 110.86,17.06 110.86,18.11 110.74,18.23 110.58,18.23 110.46,18.11 110.46,17.06 110.17,16.78 109.71,16.78 109.43,17.06 109.43,18.31 109.31,18.43 109.14,18.43 109.02,18.31 109.02,17.06 108.74,16.78 108.34,16.78 108.06,17.06 108.06,18.31 107.94,18.43 107.77,18.43 107.65,18.31 107.65,17.06 107.37,16.78 94.14,16.78 93.78,17.15 93.78,18.77 93.46,19.09 53.95,19.09 53.67,18.81 53.67,16.71 53.3,16.35 50.53,16.35 50.16,16.71 50.16,17.12 v2(49.91,17.37)
  BOTTOM w0.114: v1(161.54,55.3) 161.83,55.59 165.01,55.59 165.14,55.46 J35.7
MIPI_CSI1_CLK0N: length 172.3
  TOP w0.114: J1.41 50.47,23.05 v2(50.07,23.45) ; v1(161.54,41.91) 161.83,42.19 165.01,42.19 165.14,42.06 J36.10
  ART03 w0.102: v2(50.07,23.45) 49.79,23.17 49.65,23.17 47.1,23.17 46.61,22.68 46.61,14.65 47.65,13.6 64.86,13.6 65.38,14.12 65.38,14.9 65.58,15.1 65.98,15.1 66.1,14.98 66.1,14.32 66.39,14.04 81.51,14.04 82.68,15.2 90.36,15.2 90.7,14.86 90.7,12.17 91.11,11.76 147.66,11.76 147.94,12.04 147.94,12.68 148.06,12.8 148.23,12.8 148.35,12.68 148.35,12.04 148.63,11.76 149.03,11.76 149.31,12.04 149.31,12.68 149.43,12.8 149.6,12.8 149.72,12.68 149.72,12.04 150,11.76 150.4,11.76 150.69,12.04 150.69,12.68 150.8,12.8 150.97,12.8 151.09,12.68 151.09,12.04 151.37,11.76 151.89,11.76 155.7,15.57 155.7,41.97 155.96,42.23 161.22,42.23 v1(161.54,41.91)
MIPI_CSI1_CLK0P: length 172.3
  TOP w0.114: J36.9 165.14,42.56 165.01,42.43 161.83,42.43 v1(161.54,42.72) ; J1.39 v2(50.07,22.61)
  ART03 w0.102: v2(50.07,22.61) 49.79,22.89 49.51,22.89 49.28,22.89 arc(49.2,22.86) 49.17,22.78 arc(49.13,22.7) 49.06,22.67 48.87,22.67 arc(48.79,22.7) 48.76,22.78 arc(48.73,22.86) 48.65,22.89 48.46,22.89 arc(48.39,22.86) 48.35,22.78 arc(48.32,22.7) 48.24,22.67 48.06,22.67 arc(47.98,22.7) 47.95,22.78 arc(47.92,22.86) 47.84,22.89 47.22,22.89 46.89,22.56 46.89,14.76 47.77,13.88 64.74,13.88 65.1,14.24 65.1,15.02 65.47,15.38 66.1,15.38 66.38,15.1 66.38,14.43 66.5,14.32 81.39,14.32 82.56,15.48 90.47,15.48 90.98,14.98 90.98,12.28 91.23,12.04 147.54,12.04 147.66,12.16 147.66,12.8 147.95,13.08 148.35,13.08 148.63,12.8 148.63,12.16 148.75,12.04 148.92,12.04 149.03,12.16 149.03,12.8 149.32,13.08 149.72,13.08 150,12.8 150,12.16 150.12,12.04 150.29,12.04 150.41,12.16 150.41,12.8 150.69,13.08 151.09,13.08 151.37,12.8 151.37,12.16 151.49,12.04 151.78,12.04 155.42,15.68 155.42,42.09 155.84,42.51 157.15,42.51 arc(157.23,42.55) 157.27,42.64 arc(157.31,42.73) 157.4,42.76 157.55,42.76 arc(157.64,42.73) 157.68,42.64 arc(157.72,42.55) 157.81,42.51 157.96,42.51 arc(158.05,42.55) 158.08,42.64 arc(158.12,42.73) 158.21,42.76 158.36,42.76 arc(158.45,42.73) 158.49,42.64 arc(158.53,42.55) 158.62,42.51 158.77,42.51 arc(158.86,42.55) 158.9,42.64 arc(158.93,42.73) 159.02,42.76 159.18,42.76 arc(159.27,42.73) 159.3,42.64 arc(159.34,42.55) 159.43,42.51 159.58,42.51 arc(159.67,42.55) 159.71,42.64 arc(159.75,42.73) 159.84,42.76 159.99,42.76 arc(160.08,42.73) 160.12,42.64 arc(160.15,42.55) 160.24,42.51 160.4,42.51 arc(160.49,42.55) 160.52,42.64 arc(160.56,42.73) 160.65,42.76 160.8,42.76 arc(160.89,42.73) 160.93,42.64 arc(160.97,42.55) 161.06,42.51 161.33,42.51 v1(161.54,42.72)
MIPI_CSI1_CLK1N: length 188.2
  TOP w0.114: J1.27 47.67,22.26 47.59,22.34 47.59,23.39 47.14,23.84 44.62,23.84 v2(44.35,24.11)
  ART03 w0.102: v2(44.35,24.11) 44.07,23.83 43.11,23.83 42.74,23.47 42.74,13.39 47.09,9.05 50.24,9.05 50.53,9.33 50.53,9.65 50.65,9.77 50.81,9.77 50.93,9.65 50.93,9.33 51.22,9.05 51.62,9.05 51.9,9.33 51.9,9.65 52.02,9.77 52.19,9.77 52.3,9.65 52.3,9.33 52.59,9.05 52.99,9.05 53.27,9.33 53.27,9.65 53.39,9.77 53.56,9.77 53.68,9.65 53.68,9.33 53.96,9.05 54.36,9.05 54.64,9.33 54.64,9.65 54.76,9.77 54.93,9.77 55.05,9.65 55.05,9.33 55.33,9.05 55.73,9.05 56.01,9.33 56.01,9.65 56.13,9.77 56.3,9.77 56.42,9.65 56.42,9.33 56.7,9.05 57.16,9.05 57.45,9.33 57.45,10.64 57.56,10.76 57.73,10.76 57.85,10.64 57.85,9.33 58.13,9.05 58.53,9.05 58.82,9.33 58.82,10.64 58.94,10.76 59.1,10.76 59.22,10.64 59.22,9.33 59.51,9.05 72.58,9.05 72.95,9.42 72.95,11.22 73.15,11.42 87.84,11.42 88.16,11.1 88.16,9.42 88.53,9.06 153.7,9.06 158.62,13.98 158.62,36.06 158.84,36.27 159.16,36.27 159.27,36.15 159.27,35.58 159.56,35.3 159.96,35.3 160.24,35.58 160.24,36.15 160.36,36.27 163.59,36.27 163.96,36.64 163.96,39.13 163.56,39.52 163.03,39.52 163.02,39.51 v1(162.81,39.72)
  BOTTOM w0.114: J37.10 165.15,39.56 165.02,39.43 163.1,39.43 v1(162.81,39.72)
MIPI_CSI1_CLK1P: length 188.1
  TOP w0.114: v2(44.35,23.33) 44.62,23.6 47.04,23.6 47.35,23.29 47.35,22.34 47.27,22.26 J1.25
  ART03 w0.102: v2(44.35,23.33) 44.12,23.55 43.23,23.55 43.02,23.35 43.02,23.12 arc(43.06,23.03) 43.15,22.99 arc(43.24,22.96) 43.28,22.86 43.28,22.72 arc(43.24,22.63) 43.15,22.59 arc(43.06,22.55) 43.02,22.46 43.02,22.31 arc(43.06,22.22) 43.15,22.18 arc(43.24,22.14) 43.28,22.05 43.28,21.9 arc(43.24,21.81) 43.15,21.77 arc(43.06,21.74) 43.02,21.65 43.02,21.5 arc(43.06,21.41) 43.15,21.37 arc(43.24,21.33) 43.28,21.24 43.28,21.09 arc(43.24,21) 43.15,20.96 arc(43.06,20.92) 43.02,20.83 43.02,20.68 arc(43.06,20.59) 43.15,20.56 arc(43.24,20.52) 43.28,20.43 43.28,20.28 arc(43.24,20.19) 43.15,20.15 arc(43.06,20.11) 43.02,20.02 43.02,19.87 arc(43.06,19.78) 43.15,19.74 arc(43.24,19.7) 43.28,19.61 43.28,19.47 arc(43.24,19.37) 43.15,19.34 arc(43.06,19.3) 43.02,19.21 43.02,13.51 47.2,9.33 50.13,9.33 50.25,9.45 50.25,9.77 50.53,10.05 50.93,10.05 51.21,9.77 51.21,9.45 51.33,9.33 51.5,9.33 51.62,9.45 51.62,9.77 51.9,10.05 52.3,10.05 52.58,9.77 52.58,9.45 52.7,9.33 52.87,9.33 52.99,9.45 52.99,9.77 53.27,10.05 53.67,10.05 53.96,9.77 53.96,9.45 54.07,9.33 54.24,9.33 54.36,9.45 54.36,9.77 54.64,10.05 55.04,10.05 55.33,9.77 55.33,9.45 55.45,9.33 55.61,9.33 55.73,9.45 55.73,9.77 56.02,10.05 56.42,10.05 56.7,9.77 56.7,9.45 56.82,9.33 57.05,9.33 57.17,9.45 57.17,10.76 57.45,11.04 57.85,11.04 58.13,10.76 58.13,9.45 58.25,9.33 58.42,9.33 58.54,9.45 58.54,10.76 58.82,11.04 59.22,11.04 59.5,10.76 59.5,9.45 59.62,9.33 72.47,9.33 72.67,9.53 72.67,11.33 73.04,11.7 87.96,11.7 88.44,11.22 88.44,9.54 88.65,9.34 153.58,9.34 158.34,14.1 158.34,36.17 158.72,36.55 159.27,36.55 159.55,36.27 159.55,35.69 159.67,35.57 159.84,35.57 159.96,35.69 159.96,36.27 160.24,36.55 163.47,36.55 163.68,36.76 163.68,37.26 arc(163.63,37.37) 163.53,37.41 arc(163.42,37.46) 163.37,37.57 163.37,37.67 arc(163.42,37.77) 163.53,37.82 arc(163.63,37.86) 163.68,37.97 163.68,38.07 arc(163.63,38.18) 163.53,38.23 arc(163.42,38.27) 163.37,38.38 163.37,38.48 arc(163.42,38.59) 163.53,38.63 arc(163.63,38.68) 163.68,38.78 163.68,39.01 163.45,39.24 163.15,39.24 v1(162.81,38.91)
  BOTTOM w0.114: v1(162.81,38.91) 163.1,39.19 165.02,39.19 165.15,39.06 J37.9
MIPI_CSI1_D0N: length 172.4
  TOP w0.114: v2(51.67,23.45) 52.07,23.05 J1.49 ; v1(160.02,40.91) 160.31,41.19 165.01,41.19 165.14,41.06 J36.12
  ART03 w0.102: v2(51.67,23.45) 51.54,23.59 51.54,24.67 51.17,25.03 46.32,25.03 45.8,24.51 45.8,14.21 47.42,12.59 68.85,12.59 69.56,13.3 82.22,13.3 83.29,14.37 89.6,14.37 89.87,14.1 89.87,11.2 90.15,10.92 152.24,10.92 156.44,15.12 156.44,40.91 156.72,41.19 159.74,41.19 v1(160.02,40.91)
MIPI_CSI1_D0P: length 172.4
  TOP w0.114: J36.11 165.14,41.56 165.01,41.43 164.77,41.43 arc(164.68,41.47) 164.64,41.57 arc(164.6,41.66) 164.51,41.7 164.31,41.7 arc(164.22,41.66) 164.18,41.57 arc(164.14,41.47) 164.05,41.43 163.86,41.43 arc(163.76,41.47) 163.72,41.57 arc(163.69,41.66) 163.59,41.7 163.4,41.7 arc(163.31,41.66) 163.27,41.57 arc(163.23,41.47) 163.14,41.43 160.31,41.43 v1(160.02,41.72) ; J1.47 v2(51.67,22.61)
  ART03 w0.102: v1(160.02,41.72) 159.77,41.47 159.54,41.47 arc(159.45,41.5) 159.41,41.59 arc(159.37,41.68) 159.28,41.72 159.13,41.72 arc(159.04,41.68) 159,41.59 arc(158.97,41.5) 158.88,41.47 158.72,41.47 arc(158.63,41.5) 158.6,41.59 arc(158.56,41.68) 158.47,41.72 158.32,41.72 arc(158.23,41.68) 158.19,41.59 arc(158.15,41.5) 158.06,41.47 157.48,41.47 arc(157.42,41.49) 157.4,41.56 arc(157.37,41.62) 157.31,41.65 157.08,41.65 arc(157.02,41.62) 156.99,41.56 arc(156.96,41.49) 156.9,41.47 156.6,41.47 156.16,41.02 156.16,15.24 152.12,11.2 90.26,11.2 90.14,11.32 90.14,14.21 89.71,14.65 83.17,14.65 82.1,13.58 69.44,13.58 68.73,12.87 47.54,12.87 46.08,14.33 46.08,24.4 46.43,24.75 51.05,24.75 51.26,24.55 51.26,23.03 v2(51.67,22.61)
MIPI_CSI1_D1N: length 172.4
  TOP w0.114: J36.8 165.14,43.06 165.01,43.19 163.74,43.19 v1(163.45,42.91) ; J1.45 51.27,23.05 v2(50.87,23.45)
  ART03 w0.102: v1(163.45,42.91) 163.18,43.17 155.42,43.17 154.91,42.66 154.91,15.91 153.01,14.01 92.19,14.01 91.82,14.38 91.82,15.94 91.62,16.14 64.72,16.14 64.47,15.89 64.47,14.75 64.06,14.34 63.51,14.34 63.23,14.62 63.23,15.69 63.11,15.81 62.94,15.81 62.82,15.69 62.82,14.62 62.54,14.34 62.14,14.34 61.86,14.62 61.86,15.69 61.74,15.81 61.57,15.81 61.45,15.69 61.45,14.62 61.17,14.34 60.77,14.34 60.49,14.62 60.49,15.69 60.37,15.81 60.2,15.81 60.08,15.69 60.08,14.62 59.8,14.34 59.28,14.34 59,14.62 59,15.26 58.88,15.38 58.71,15.38 58.59,15.26 58.59,14.62 58.31,14.34 48.18,14.34 47.47,15.05 47.47,21.75 47.84,22.11 50.27,22.11 50.47,22.32 50.47,23.05 v2(50.87,23.45)
MIPI_CSI1_D1P: length 172.4
  TOP w0.114: J36.7 165.14,43.56 165.01,43.43 163.74,43.43 v1(163.45,43.72) ; J1.43 v2(50.87,22.61)
  ART03 w0.102: v1(163.45,43.72) 163.18,43.45 162.16,43.45 arc(162.07,43.49) 162.04,43.58 arc(161.98,43.7) 161.86,43.75 161.81,43.75 arc(161.68,43.7) 161.63,43.58 arc(161.59,43.49) 161.5,43.45 161.35,43.45 arc(161.26,43.49) 161.22,43.58 arc(161.19,43.67) 161.1,43.7 160.94,43.7 arc(160.85,43.67) 160.82,43.58 arc(160.78,43.49) 160.69,43.45 160.54,43.45 arc(160.45,43.49) 160.41,43.58 arc(160.37,43.67) 160.28,43.7 160.13,43.7 arc(160.04,43.67) 160,43.58 arc(159.97,43.49) 159.88,43.45 159.72,43.45 arc(159.63,43.49) 159.6,43.58 arc(159.56,43.67) 159.47,43.7 159.32,43.7 arc(159.23,43.67) 159.19,43.58 arc(159.15,43.49) 159.06,43.45 158.91,43.45 arc(158.82,43.49) 158.78,43.58 arc(158.75,43.67) 158.66,43.7 158.5,43.7 arc(158.41,43.67) 158.38,43.58 arc(158.34,43.49) 158.25,43.45 158.1,43.45 arc(158.01,43.49) 157.97,43.58 arc(157.93,43.67) 157.84,43.7 157.69,43.7 arc(157.6,43.67) 157.56,43.58 arc(157.53,43.49) 157.44,43.45 155.31,43.45 154.64,42.78 154.64,16.03 152.9,14.29 92.3,14.29 92.1,14.49 92.1,16.06 91.73,16.42 64.6,16.42 64.19,16.01 64.19,14.86 63.94,14.62 63.63,14.62 63.51,14.74 63.51,15.81 63.23,16.09 62.83,16.09 62.54,15.81 62.54,14.74 62.42,14.62 62.26,14.62 62.14,14.74 62.14,15.81 61.85,16.09 61.45,16.09 61.17,15.81 61.17,14.74 61.05,14.62 60.88,14.62 60.77,14.74 60.77,15.81 60.48,16.09 60.08,16.09 59.8,15.81 59.8,14.74 59.68,14.62 59.4,14.62 59.28,14.74 59.28,15.38 59,15.66 58.6,15.66 58.31,15.38 58.31,14.74 58.19,14.62 48.3,14.62 47.75,15.17 47.75,21.63 47.96,21.83 48.66,21.83 arc(48.75,21.8) 48.78,21.71 arc(48.82,21.62) 48.91,21.58 49.06,21.58 arc(49.15,21.62) 49.19,21.71 arc(49.23,21.8) 49.32,21.83 49.47,21.83 arc(49.56,21.8) 49.6,21.71 arc(49.63,21.62) 49.72,21.58 49.87,21.58 arc(49.96,21.62) 50,21.71 arc(50.04,21.8) 50.13,21.83 50.38,21.83 50.75,22.2 50.75,22.49 v2(50.87,22.61)
MIPI_CSI1_D2N: length 188.1
  TOP w0.114: v2(42.29,26.83) 42.56,26.56 48.75,26.56 49.59,25.72 49.59,22.34 49.67,22.26 J1.37
  ART03 w0.102: v2(42.29,26.83) 42.04,26.58 41.64,26.58 41.27,26.21 41.27,13.33 46.29,8.31 154.24,8.31 159.36,13.44 159.36,33.82 159.81,34.26 164.08,34.26 164.92,35.1 164.92,39.96 164.43,40.45 161.81,40.45 v1(161.54,40.72)
  BOTTOM w0.114: v1(161.54,40.72) 161.83,40.43 165.02,40.43 165.15,40.56 J37.12
MIPI_CSI1_D2P: length 188
  TOP w0.114: v2(42.29,26.05) 42.56,26.32 48.65,26.32 49.35,25.62 49.35,22.34 49.27,22.26 J1.35
  ART03 w0.102: v2(42.29,26.05) 42.04,26.3 41.75,26.3 41.55,26.09 41.55,25.87 arc(41.59,25.77) 41.68,25.74 arc(41.77,25.7) 41.81,25.61 41.81,25.46 arc(41.77,25.37) 41.68,25.33 arc(41.59,25.29) 41.55,25.2 41.55,25.05 arc(41.59,24.96) 41.68,24.92 arc(41.77,24.89) 41.81,24.8 41.81,24.65 arc(41.77,24.56) 41.68,24.52 arc(41.59,24.48) 41.55,24.39 41.55,24.24 arc(41.59,24.15) 41.68,24.11 arc(41.77,24.07) 41.81,23.98 41.81,23.83 arc(41.77,23.74) 41.68,23.7 arc(41.59,23.67) 41.55,23.58 41.55,23.43 arc(41.59,23.34) 41.68,23.3 arc(41.77,23.26) 41.81,23.17 41.81,23.02 arc(41.77,22.93) 41.68,22.89 arc(41.59,22.85) 41.55,22.76 41.55,13.44 46.4,8.59 154.12,8.59 159.08,13.55 159.08,33.93 159.69,34.54 163.97,34.54 164.64,35.22 164.64,36.53 arc(164.61,36.61) 164.53,36.64 arc(164.45,36.67) 164.41,36.75 164.41,36.93 arc(164.45,37.01) 164.53,37.05 arc(164.61,37.08) 164.64,37.16 164.64,37.34 arc(164.61,37.42) 164.53,37.45 arc(164.45,37.49) 164.41,37.57 164.41,37.74 arc(164.45,37.83) 164.53,37.86 arc(164.61,37.89) 164.64,37.97 164.64,38.15 arc(164.61,38.23) 164.53,38.27 arc(164.45,38.3) 164.41,38.38 164.41,38.56 arc(164.45,38.64) 164.53,38.67 arc(164.61,38.7) 164.64,38.79 164.64,38.96 arc(164.61,39.04) 164.53,39.08 arc(164.45,39.11) 164.41,39.19 164.41,39.37 arc(164.45,39.45) 164.53,39.48 arc(164.61,39.52) 164.64,39.6 164.64,39.84 164.31,40.17 161.81,40.17 v1(161.54,39.91)
  BOTTOM w0.114: v1(161.54,39.91) 161.83,40.19 165.02,40.19 165.15,40.06 J37.11
MIPI_CSI1_D3N: length 188.1
  TOP w0.114: v2(43.76,25.84) 44.03,25.57 48.31,25.57 48.79,25.09 48.79,22.34 48.87,22.26 J1.33
  ART03 w0.102: v2(43.76,25.84) 44.01,25.59 44.74,25.59 45.11,25.21 45.11,13.25 46.58,11.78 59.97,11.78 60.3,11.44 60.3,10.27 60.5,10.07 61.88,10.07 62,10.18 62,11.57 62.29,11.85 62.69,11.85 62.97,11.57 62.97,10.18 63.09,10.07 64.45,10.07 64.55,10.17 64.55,11.48 64.84,11.78 65.25,11.78 65.52,11.51 65.52,10.17 65.62,10.07 66.98,10.07 67.1,10.18 67.1,11.34 67.38,11.62 67.78,11.62 68.06,11.34 68.06,10.18 68.18,10.07 69.52,10.07 69.72,10.27 69.72,12.12 70.04,12.44 70.55,12.44 70.83,12.15 70.83,10.17 70.95,10.05 71.6,10.05 71.7,10.15 71.7,12.17 71.97,12.44 88.43,12.44 89.2,11.66 89.2,10.28 89.41,10.07 153.2,10.07 157.58,14.45 157.58,38.03 158.01,38.45 161.12,38.45 v1(161.39,38.72)
  BOTTOM w0.114: v1(161.39,38.72) 161.68,38.43 165.02,38.43 165.15,38.56 J37.8
MIPI_CSI1_D3P: length 188.2
  TOP w0.114: v2(43.76,25.06) 44.03,25.33 48.21,25.33 48.55,24.99 48.55,22.34 48.47,22.26 J1.31
  ART03 w0.102: v2(43.76,25.06) 44.01,25.31 44.62,25.31 44.83,25.1 44.83,13.13 46.47,11.5 59.85,11.5 60.02,11.33 60.02,10.15 60.39,9.79 62,9.79 62.28,10.07 62.28,11.45 62.4,11.57 62.57,11.57 62.69,11.45 62.69,10.07 62.97,9.79 64.57,9.79 64.83,10.05 64.83,11.37 64.96,11.5 65.14,11.5 65.24,11.39 65.24,10.05 65.5,9.79 67.09,9.79 67.38,10.07 67.38,11.22 67.49,11.34 67.66,11.34 67.78,11.22 67.78,10.07 68.06,9.79 69.64,9.79 70,10.15 70,12 70.15,12.16 70.43,12.16 70.55,12.04 70.55,10.05 70.84,9.77 71.72,9.77 71.98,10.03 71.98,12.05 72.09,12.16 88.32,12.16 88.93,11.55 88.93,10.16 89.29,9.79 153.32,9.79 157.86,14.34 157.86,37.91 158.12,38.17 159.49,38.17 arc(159.55,38.15) 159.58,38.08 arc(159.61,38.02) 159.67,37.99 159.89,37.99 arc(159.96,38.02) 159.99,38.08 arc(160.01,38.15) 160.08,38.17 160.3,38.17 arc(160.36,38.15) 160.39,38.08 arc(160.42,38.02) 160.48,37.99 160.7,37.99 arc(160.77,38.02) 160.8,38.08 arc(160.83,38.15) 160.89,38.17 161.12,38.17 v1(161.39,37.91)
  BOTTOM w0.114: v1(161.39,37.91) 161.68,38.19 165.02,38.19 165.15,38.06 J37.7
MIPI_DPHY0_RX_CLKN: length 147.8
  TOP w0.114: v2(45.46,63.56) 45.19,63.83 45.19,64.42 45.27,64.5 J3.15 ; v1(158.6,76.94) 158.6,77.21 158.72,77.33 159.26,77.33 159.5,77.09 159.5,76.08 159.77,75.81 160.16,75.81 160.44,76.08 160.44,77.09 160.57,77.23 162.07,77.23 162.32,76.98 163.98,76.98 arc(164.07,76.94) 164.11,76.85 arc(164.14,76.76) 164.23,76.72 164.44,76.72 arc(164.53,76.76) 164.56,76.85 arc(164.6,76.94) 164.69,76.98 164.93,76.98 arc(165,76.96) 165.07,76.92 165.08,76.9 arc(165.15,76.86) 165.22,76.85 J32.10
  ART03 w0.102: v2(45.46,63.56) 45.21,63.31 45.21,61.33 45.49,61.05 51.71,61.05 55.75,65.09 65.39,65.09 69.03,61.46 75.02,61.46 78.04,60.93 81.05,61.46 81.93,61.46 84.66,60.98 87.39,61.46 88.25,61.46 92.28,62.16 96.32,61.46 100.3,61.46 103.7,62.05 107.09,61.46 114.1,61.46 114.3,61.66 114.3,62.91 114.32,63.15 114.68,65.22 114.32,67.29 114.3,67.54 114.3,70.18 117.84,73.73 123.34,73.73 123.8,74.18 140.26,74.18 140.46,74.39 140.46,76.38 140.83,76.75 148.41,76.75 149.05,76.11 157.36,76.11 arc(157.45,76.15) 157.49,76.24 arc(157.52,76.33) 157.61,76.37 157.77,76.37 arc(157.86,76.33) 157.89,76.24 arc(157.93,76.15) 158.02,76.11 158.17,76.11 arc(158.26,76.15) 158.3,76.24 arc(158.34,76.33) 158.43,76.37 158.58,76.37 arc(158.67,76.33) 158.71,76.24 arc(158.74,76.15) 158.83,76.11 159.23,76.11 159.44,76.32 159.44,77.01 159.16,77.28 158.7,77.28 158.6,77.18 v1(158.6,76.94)
